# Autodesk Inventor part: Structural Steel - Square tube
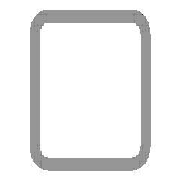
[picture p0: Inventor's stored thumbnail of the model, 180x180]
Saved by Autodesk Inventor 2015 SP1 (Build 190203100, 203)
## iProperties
IsCustomPart: 1
Created: 2011-06
Part Number: Structural Steel - Square tube
Material: Stainless Steel
Document SubType Name: Modeling
Standard: ISO
Designer: Guilherme Augusto Franco de Souza
Standard Revision: Second edition 2001-09-01
Standards Organization: ISO
Language: en-US
Size Designation: 25x25x2
Categories: <MemberInstance><Categories><Category DisplayName="Structural Shapes" InternalName="089c4875-fa83-4c05-b084-43b9cc11f5ed" Mnemonic="GRDR"><CategoryParameter Dis
Stock Number: 25x25x2
Density: 8.08 g/cm^3
Description: ISO 4019 - 25x25x2
Appearance: Steel
G_L: 700,000 mm
G_W: 25,000 mm
G_H: 25,000 mm
+B89455D9-CC8F-490E-ADB0-AB19616D39C9+CUTDETAIL1: Miter 45,00 deg
+3F952AE1-E171-4758-B047-084C1F7F7CE4+CUTDETAIL2: Miter 45,00 deg
Author: Guilherme Augusto Franco de Souza
_CCFamilyMember: 2
_CCFamilyDisplayName: ISO 4019 (Square) - Structural steels - Cold-formed, welded, structural hollow sections
_FrameMemberDoc: Frame Member File
_Version: 15.0.0
_GetPNFromCC: 1
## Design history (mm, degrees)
node "Start plane"
node "End plane"
sketch "Sketch"
  geometry: L1 (-12.5, -8.5)-(-12.5, 8.5); L2 (-8.5, 12.5)-(8.5, 12.5); L3 (12.5, 8.5)-(12.5, -8.5); L4 (8.5, -12.5)-(-8.5, -12.5); L5 (-8.5, 10.5)-(8.5, 10.5); L6 (10.5, 8.5)-(10.5, -8.5); L7 (8.5, -10.5)-(-8.5, -10.5); L8 (-10.5, -8.5)-(-10.5, 8.5); L9 (0, 18.66)-(0, -18.66) reference; L10 (-18.66, 0)-(18.66, 0) reference; A1 r 4 centre (-8.5, -8.5) between (-12.5, -8.5) and (-8.5, -12.5); A2 r 4 centre (8.5, 8.5) between (12.5, 8.5) and (8.5, 12.5); A3 r 4 centre (-8.5, 8.5) between (-8.5, 12.5) and (-12.5, 8.5); A4 r 4 centre (8.5, -8.5) between (8.5, -12.5) and (12.5, -8.5); A5 r 2 centre (-8.5, 8.5) between (-8.5, 10.5) and (-10.5, 8.5); A6 r 2 centre (8.5, 8.5) between (10.5, 8.5) and (8.5, 10.5); A7 r 2 centre (8.5, -8.5) between (8.5, -10.5) and (10.5, -8.5); A8 r 2 centre (-8.5, -8.5) between (-10.5, -8.5) and (-8.5, -10.5)
  constraints: 16 end point, 16 point on circle, 8 centre point, 8 tangent, 4 parallel, 3 equal radius, 2 perpendicular, 7 other
  dimensions: "d7" = 4 radius of A1 (= G_IR); "d9" = 25 distance between parallel lines of L1 L3 (= G_W); "d11" = 25 distance between parallel lines of L2 L4 (= G_H); "d12" = 2 distance between parallel lines of L3 L6 (= G_T); "d15" = 12.5 distance between parallel lines of L9 L3 (= 0.5 x d9); "d16" = 12.5 distance between parallel lines of L2 L10 (= 0.5 x d11)
extrude "Body" new body sketch "Sketch" stored distance "d3" = 700 (= G_L); taper "d4" = 0 deg
node "Driven Length"
  sketch "Sketch3"
    geometry: L1 (0, 0)-(10, 0) reference
    constraints: 2 end point, 1 horizontal
  workplane "Work Plane3"
  sketch "Sketch4"
    geometry: L1 (-2, 0.141)-(12, 0.141) reference; L2 (-2, 699.859)-(12, 699.859) reference
    dimensions: "d18" = 699.71716 distance between parallel lines of L1 L2 (derived)
workplane "Work Plane4"
split "Split1"
workplane "Work Plane5"
split "Split2"
body "Solid1"
other parameters: "G_W" = 25 [user parameter; used in 1 equation term], "G_H" = 25 [user parameter; used in 1 equation term], "G_T" = 2 [user parameter; used in 1 equation term], "G_IR" = 4 [user parameter; used in 1 equation term], "G_L" = 700 [user parameter; used in 1 equation term], "G_OFFSET_START" = -0.14142 [user parameter; used in 1 equation term], "G_OFFSET_END" = -0.14142 [user parameter; used in 1 equation term], "d13" = 0.14142 (= -G_OFFSET_START), "d14" = 699.85858 (= G_OFFSET_END + B_L), "d17" = 90 deg, "MAS" = 0.136 [user parameter]
